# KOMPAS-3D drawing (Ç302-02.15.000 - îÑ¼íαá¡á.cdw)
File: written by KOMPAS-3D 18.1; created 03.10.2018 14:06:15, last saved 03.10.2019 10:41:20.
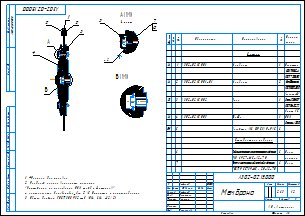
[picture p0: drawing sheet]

Sheet 1: A3, landscape

Document properties: Автор: Милов; Масса: 2.62614; Полное имя файла: ..\А302-01.15.000 - Мембрана.a3d

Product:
- Part/product: (unnamed)
  - Component: Мембрана  | designation А302-02.15.001  | pos. 1  | Раздел спецификации: Детали; Форматы листов документа: А4; Примечание: Пластина /  ІФ-IІ ТМКЩ-C-4  / ГОСТ 7338-90
  - Component: Мембрана  | designation А302-02.15.001-01  | pos. 2  | Раздел спецификации: Детали; Форматы листов документа: А4; Примечание: Лист Фторопласт-4  / ГОСТ 10007-80 Е / "каленный"
  - Component: Упор  | designation А302-02.15.002  | pos. 3  | Раздел спецификации: Детали; Форматы листов документа: А3; Примечание: Сталь 12Х18Н10Т  / ГОСТ 5632-72 / Лист 15
  - Component: Шайба  | designation А302-02.15.003  | pos. 4  | Раздел спецификации: Детали; Форматы листов документа: А4; Примечание: ПВХ / Стержень @2~300
  - Component: Заглушка @2~16 FIP CIV R-PVC  | pos. 5  | Раздел спецификации: Детали; Форматы листов документа: БЧ
  - Component: Гайка шестигранная самостопорящаяся с фланцем / DIN 6927-M5-A2-70  | pos. 6  | Раздел спецификации: Стандартные изделия; Примечание: Нерж. / насечки
  - Component: Болт с шестигранной головкой с фланцем  / ГОСТ Р 55739-М5 x 20-A2-70  | pos. 7  | Раздел спецификации: Стандартные изделия; Примечание: Нерж.

Title block, sheet 1: Наименование: Мембрана; designation: А302-02.15.000; Масса: 2,63; scale: 1:2; Количество листов документа: 1; organisation: АО «Астерион»; Форматы листов документа: A3; stored path: \\192.168.87.28\Konstructor_doc\Мембранные насосы\Мембранный электропривод\А302-00.00.000 - ASTRA-302 (МЭ200)\3Д ПВХ\А302-01.15.000 - Мембрана.cdw; Разработал: Лифлянд; Проверил: Борисенко; Т. контр.: Лучихин; Утвердил: Григорьева

Views: Вид 1, Местный разрез 1, Вид:2, Выносной элемент 3, Выносной элемент 4, Выносной элемент А, Выносной элемент, Выносной элемент Б
Referenced files in D:\Мембранные насосы\Мембранный электропривод\А302-00.00.000 - ASTRA-302 (МЭ200)\3Д ПВХ\: А302-01.15.001-01- Мембрана.m3d, А302-01.15.007 - Заглушка.m3d, А302-01.15.001 - Мембрана.m3d, А302-01.15.002 - Упор.a3d, А302-01.15.003 - Шайба.m3d, А302-01.15.000 - Мембрана.a3d, А302-01.15.001 - Мембрана.cdw, А302-01.15.002 - Упор.m3d, А302-01.15.008 - Кольцо плоское Ф4.m3d, А302-01.15.008 - Кольцо плоское уплотнительное 5-13-10 Ф4.cdw, А302-01.15.009 - Кольцо плоское Ф4.m3d, А302-01.15.007 - Заглушка.cdw, А302-01.15.011 - Заглушка резьбовая.m3d, А302-01.15.011 - Заглушка резьбовая.cdw
Referenced files in Z:\Мембранные насосы\Мембранный электропривод\А302-00.00.000 - ASTRA-302 (МЭ200)\3Д ПВХ\: А302-01.15.000 - Мембрана.a3d, А302-01.15.008 - Кольцо плоское Ф4.m3d
Referenced files in D:\2 Стандартные изделия 3D\Гайки\DIN 6927\: Гайка шестигранная самостопорящаяся с фланцем DIN 6927-M5 - A2-70.m3d
Referenced files in \\192.168.87.28\Konstructor_doc\Мембранные насосы\Мембранный электропривод\А302-00.00.000 - ASTRA-302 (МЭ200)\3Д ПВХ\: А302-01.15.011 - Заглушка резьбовая.cdw
Referenced files in D:\Мембранные насосы\Мембранный электропривод\А302-00.00.000 - ASTRA-302 (МЭ200)\Чертежи ПВХ\: А302-02.15.002 - Упор.cdw
Referenced files in C:\Program Files\ASCON\KOMPAS-3D v18\Libs\PartLib\DATA\VAULT\methods\kompas\3d\: PLib_Bolt_1_ISO_1100.m3d, PLib_Nut_ISO_1100.m3d
Referenced files in C:\Program Files\ASCON\KOMPAS-3D V16\Libs\PartLib\DATA\vault\Methods\Kompas\3D\: PLib_Nut_ISO_1100.m3d, PLib_Bolt_1_ISO_1100.m3d
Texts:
  Шайба
  Упор
  Болт с шестигранной головкой с фланцем
  ГОСТ Р  55739-М5 x 25-A2-70
  ГОСТ
  Нерж.
  Нержавеющая сталь
  Гайка шестигранная самостопорящаяся с фланцем
  DIN 6927-M5-A2-70
  Гайка
  шестигранная
  самостопорящаяся
  фланцем
  DIN
  насечки
  Нерж. / насечки
  Кольцо плоское
  уплотнительное 5-13-10 Ф4
  Кольцо плоское  / уплотнительное 5-13-10 Ф4
  ГОСТ Р  55739-М8 x 30-A2-70
  Кольцо плоское Ф4
  Заглушка
  Заглушка резьбовая
  Лента ФУМ
  Лента
  ФУМ
  3D_Doc-graphic.lyt,1.000000-4294967295-203648116615
  Болт с шестигранной головкой с фланцем ГОСТ Р 55739-М5 x 20-A2-70
  Болт
  шестигранной
  головкой
  Пластина
  ІФ-IІ ТМКЩ-C-4
  ГОСТ 7338-90
  Пластина /  ІФ-IІ ТМКЩ-C-4  / ГОСТ 7338-90
  Лист Фторопласт-4
  ГОСТ 10007-80 Е
  "каленный"
  Лист Фторопласт-4  / ГОСТ 10007-80 Е / "каленный"
  Сталь 12Х18Н10Т
  ГОСТ 5632-72
  Лист 15
  Сталь 12Х18Н10Т  / ГОСТ 5632-72 / Лист 15
  ПВХ
  Стержень  300
  ПВХ / Стержень @2~300
  Заглушка  16 FIP CIV R-PVC
  Заглушка @2~16 FIP CIV R-PVC
  ГОСТ Р 55739-М5 x 20-A2-70
  Гайка шестигранная с фланцем ГОСТ Р ИСО 4161 - M5 - A2-70
  Гайка шестигранная самостопорящаяся с фланцем / DIN 6927-M5-A2-70
  Болт с шестигранной головкой с фланцем ГОСТ Р 55739-М8 x 16-A2-70
Dimensions and other numbers on the sheet: 2; 1; 3; 4; 6 мест; 5; 7; 8; 10; 9; 6; 11; 12; 100; 41; 48; 1:2; 2,63; 03.10.2019

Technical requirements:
  *Размеры для справок.
  Разделку кромок выполнить согласно:
  "Инструкция по склеиванию ПВХ труб и фитингов".
  - расположение Konstructor_doc Z:\5 Оснастка и приспособления
  Общие допуски ГОСТ 30893.2-mK (H14, h14,  t2/2).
